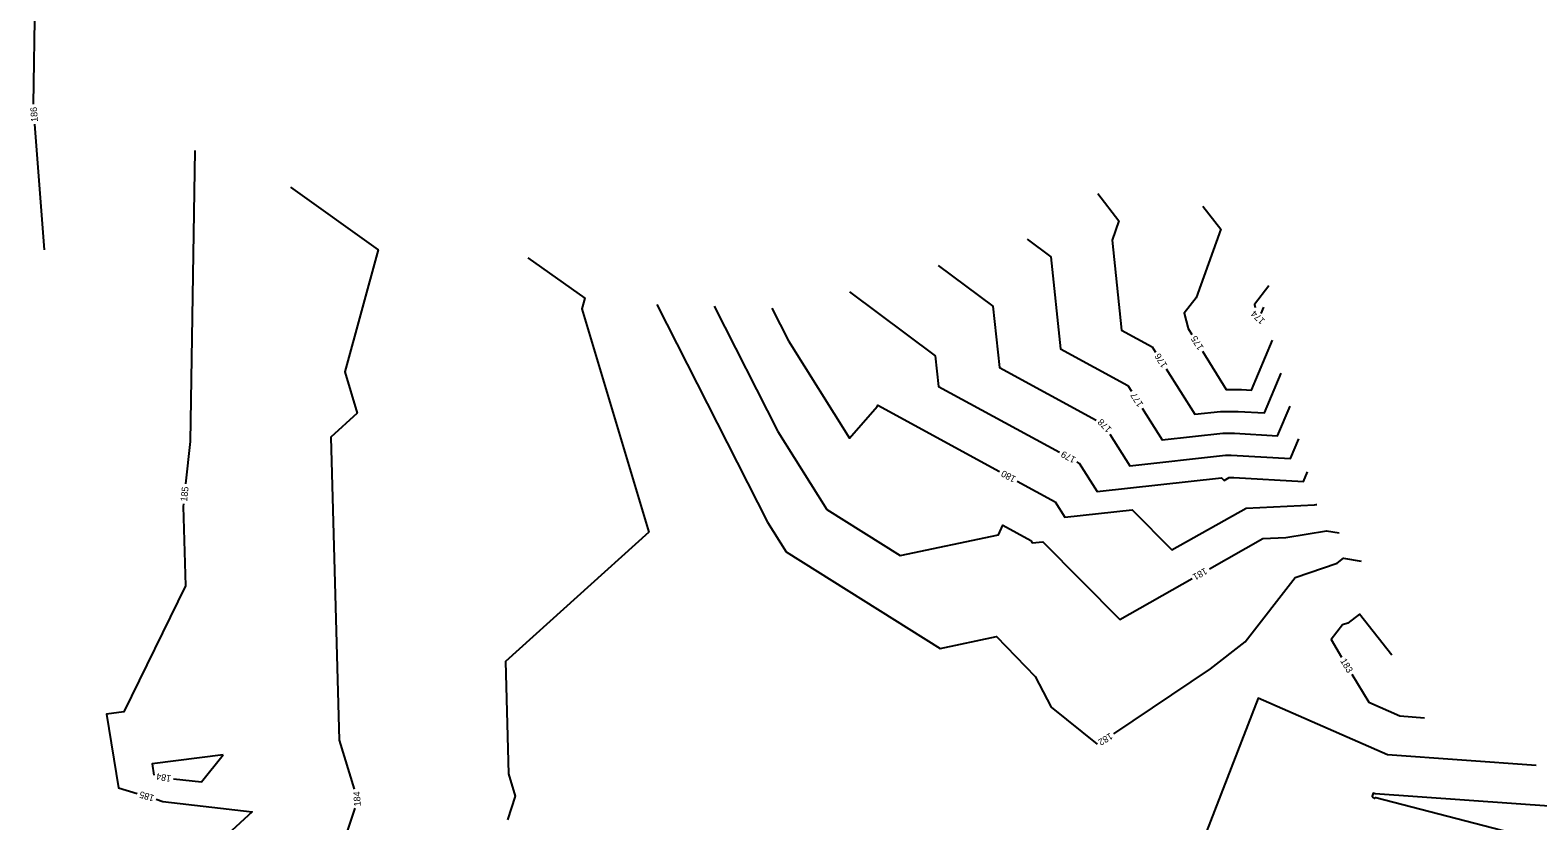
# Model space of a CAD drawing. Extents: x 2086416 to 2115205, y 575507 to 632762.
# Drawn here: x 2110467.8 to 2110919.3, y 582037.5 to 582274.4 of the extents above; entities that cross this region are included whole.
import ezdxf

# ---------------------------------------------------------------- set-up
doc = ezdxf.new("R2010")
doc.units = 0
for name, color, linetype in [('DTM Contours Major', 7, 'Continuous'), ('DTM Contours Major Text', 7, 'Continuous'), ('DTM Contours Minor', 7, 'Continuous'), ('DTM Contours Minor Text', 7, 'Continuous')]:
    doc.layers.add(name, color=color, linetype=linetype)

msp = doc.modelspace()

# ---------------------------------------------------------------- linework, layer by layer
at = {"layer": 'DTM Contours Major'}
for points in [[(2110517.12, 582238.36), (2110515.68, 582151.15), (2110514.32, 582138.44)], [(2110819.01, 582221.68), (2110824.37, 582214.73), (2110816.95, 582194.15), (2110813.38, 582189.59), (2110814.54, 582185.04), (2110815.66, 582183.25)], [(2110689.85, 582191.12), (2110694.84, 582181.32), (2110713.16, 582152.13), (2110721.45, 582161.66), (2110721.61, 582162.02), (2110758.07, 582142.16)], [(2110818.85, 582178.17), (2110826, 582166.74), (2110830.55, 582166.73), (2110833.5, 582166.56), (2110839.86, 582181.51)], [(2110763.34, 582139.29), (2110774.71, 582133.1), (2110777.64, 582128.48), (2110797.82, 582130.71), (2110809.74, 582118.68), (2110831.91, 582131.22), (2110852.37, 582132.2), (2110852.95, 582132.3), (2110853.13, 582132.27)], [(2110513.68, 582132.48), (2110513.6, 582131.73), (2110514.27, 582107.89), (2110495.85, 582070.16), (2110490.64, 582069.5), (2110494.2, 582047.45), (2110499.78, 582045.74)], [(2110505.52, 582043.98), (2110507.54, 582043.36), (2110534.29, 582040.27), (2110519.68, 582026.82), (2110495.82, 582017.05), (2110495.4, 582014.24), (2110492.28, 582007.94), (2110479.63, 581999.09)]]:
    msp.add_lwpolyline(points, dxfattribs=at)
at = {"layer": 'DTM Contours Minor'}
for points in [[(2110468.72, 582252.16), (2110469.25, 582283.86)], [(2110472.1, 582208.58), (2110469.17, 582246.17)], [(2110545.72, 582227.3), (2110572.04, 582208.53), (2110562.02, 582172.01), (2110565.74, 582159.65), (2110557.78, 582152.47), (2110560.29, 582061.73), (2110564.79, 582047)], [(2110787.48, 582225.48), (2110793.84, 582217.21), (2110791.79, 582211.51), (2110794.63, 582184.49), (2110803.78, 582179.51), (2110804.76, 582177.95)], [(2110766.33, 582211.75), (2110773.45, 582206.44), (2110776.35, 582178.89), (2110796.51, 582167.91), (2110797.59, 582166.21)], [(2110616.86, 582206.21), (2110633.87, 582194.08), (2110632.99, 582190.85), (2110653.08, 582124.04), (2110610.08, 582085.22), (2110611.01, 582051.66), (2110613.06, 582044.97), (2110610.68, 582037.87)], [(2110739.73, 582203.89), (2110756.13, 582191.65), (2110758.07, 582173.28), (2110787.03, 582157.51)], [(2110713.13, 582196.02), (2110738.82, 582176.86), (2110739.78, 582167.68), (2110776.01, 582147.95)], [(2110838.72, 582197.75), (2110834.41, 582192.24), (2110834.67, 582191.25)], [(2110655.42, 582192.2), (2110688.62, 582127.02), (2110694.2, 582118.13), (2110740.28, 582089.19), (2110757.14, 582092.76), (2110768.79, 582080.81), (2110773.54, 582071.6), (2110787.31, 582060.54)], [(2110672.63, 582191.66), (2110691.73, 582154.17), (2110706.39, 582130.82), (2110728.36, 582117.03), (2110757.81, 582123.25), (2110759.08, 582126.05), (2110767.45, 582121.49), (2110767.91, 582120.77), (2110771.09, 582121.12), (2110794.12, 582097.84), (2110815.79, 582110.11)], [(2110836.46, 582189.52), (2110837.25, 582191.38)], [(2110807.97, 582172.88), (2110816.55, 582159.34), (2110824.26, 582160.19), (2110829.51, 582160.18), (2110837.4, 582159.71), (2110842.48, 582171.65)], [(2110800.8, 582161.14), (2110806.82, 582151.62), (2110825.01, 582153.64), (2110828.47, 582153.63), (2110841.3, 582152.87), (2110845.09, 582161.79)], [(2110791.1, 582153.37), (2110797.09, 582143.91), (2110825.76, 582147.08), (2110827.43, 582147.08), (2110845.2, 582146.03), (2110847.7, 582151.93)], [(2110781.28, 582145.08), (2110781.98, 582144.7), (2110787.36, 582136.19), (2110824.56, 582140.31), (2110825.35, 582139.51), (2110826.82, 582140.35), (2110828.29, 582140.42), (2110849.09, 582139.19), (2110850.31, 582142.06)], [(2110821.02, 582113.06), (2110836.99, 582122.1), (2110843.8, 582122.43), (2110856.05, 582124.43), (2110859.78, 582123.8)], [(2110792.29, 582063.62), (2110821.3, 582083.07), (2110831.63, 582091.14), (2110846.63, 582110.43), (2110859.17, 582114.72), (2110861.13, 582116.22), (2110866.43, 582115.33)], [(2110875.6, 582087.16), (2110865.86, 582099.43), (2110862.42, 582096.79), (2110860.78, 582096.23), (2110857.4, 582091.88), (2110860.55, 582086.61)], [(2110863.62, 582081.46), (2110868.65, 582073.04), (2110877.99, 582068.94), (2110885.35, 582068.42)], [(2110918.81, 582054.12), (2110874.3, 582057.26), (2110835.52, 582074.28), (2110813.19, 582016.55), (2110832.03, 581997.68), (2110808.69, 582005)], [(2110525.53, 582057.3), (2110504.28, 582054.61), (2110504.82, 582051.25)], [(2110510.69, 582050.16), (2110519.12, 582049.19), (2110525.53, 582057.3)], [(2110952.27, 582039.82), (2110870.6, 582045.58), (2110869.99, 582045.85), (2110869.64, 582044.94), (2110870.02, 582044.56), (2110870.37, 582044.22), (2110870.78, 582044.51), (2110943.97, 582025.54), (2110912.84, 582001.48)], [(2110565.03, 582041.29), (2110554.3, 582009.3), (2110535.63, 582027.04), (2110528.79, 582020.74), (2110525.03, 582019.2), (2110522.24, 582000.56), (2110517.36, 581990.74), (2110521.39, 581944.54), (2110504.51, 581916.72), (2110502.84, 581914.77), (2110502.62, 581913.15), (2110489.56, 581907.53)]]:
    msp.add_lwpolyline(points, dxfattribs=at)

# ---------------------------------------------------------------- texts
at = {"layer": 'DTM Contours Major Text'}
for s, rotation, p in [('175', 122.0431, (2110819.31, 582179.31)), ('180', 151.424, (2110763.19, 582140.51)), ('185', 83.8942, (2110514.76, 582133.09)), ('185', 162.96, (2110505.12, 582045.15))]:
    msp.add_text(s, height=2, rotation=rotation, dxfattribs=at).set_placement(p)
at = {"layer": 'DTM Contours Minor Text'}
for s, rotation, p in [('186', 94.2425, (2110470.1, 582246.97)), ('174', 136.0843, (2110837.74, 582187.48)), ('176', 122.3385, (2110808.43, 582174.03)), ('177', 122.3385, (2110801.25, 582162.28)), ('178', 134.5384, (2110791.81, 582154.98)), ('179', 151.424, (2110781.12, 582146.3)), ('181', 209.5075, (2110819.6, 582113.41)), ('183', 300.8378, (2110860.06, 582085.47)), ('182', 211.7786, (2110791.2, 582064)), ('184', 169.5322, (2110510.13, 582051.08)), ('184', 92.4096, (2110566.76, 582041.9))]:
    msp.add_text(s, height=2, rotation=rotation, dxfattribs=at).set_placement(p)

doc.saveas('drawing.dxf')
